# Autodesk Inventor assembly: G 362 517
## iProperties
Created: 2006-10
Part Number: G 362 517
Document SubType Name: Assembly
Designer: I.Baliuc
Manufacturer: Standard
Standards Organization: Custom
Description: Isolator, kpl.
Mass: 928.896 g
Surface Area: 1540.96 cm^2
Volume: 670.581 cm^3
Density: 1.38521 g/cm^3
Title: Isolator
Company: Mayer & Müller AG Schaltgeräte
Zweck: HN / HE 2000 DC
Author: T.Messerschmitt
Revision Number: 362517
